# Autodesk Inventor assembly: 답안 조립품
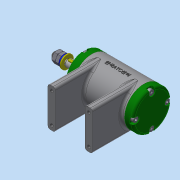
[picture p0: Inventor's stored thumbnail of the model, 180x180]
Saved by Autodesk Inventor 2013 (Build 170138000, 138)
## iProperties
Created: 2020-07
Part Number: 답안 조립품
Document SubType Name: Assembly
Designer: dgall
Author: dgall
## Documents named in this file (15)
- C:\Users\dgall\Desktop\700706V1017\답안 조립품.iam
- C:\Users\dgall\Desktop\700706V1017\본체.ipt
- C:\Users\dgall\Desktop\700706V1017\베어링 6002.ipt
- C:\Users\dgall\Desktop\700706V1017\뒤커버.ipt
- C:\Users\dgall\Desktop\700706V1017\앞커버.ipt
- C:\Users\dgall\Desktop\700706V1017\축.ipt
- C:\Users\dgall\Desktop\700706V1017\오일 실 15 25 7.ipt
- C:\Users\dgall\Desktop\700706V1017\키 3x3x12.ipt
- C:\Users\dgall\Desktop\700706V1017\V벨트풀리.ipt
- C:\Users\dgall\Desktop\700706V1017\와셔 8x17.ipt
- C:\Users\dgall\Desktop\700706V1017\스프링와셔 8.ipt
- C:\Users\dgall\Desktop\700706V1017\너트 M8.ipt
- C:\Users\dgall\Desktop\700706V1017\와셔 6x11.5.ipt
- C:\Users\dgall\Desktop\700706V1017\볼트 M6x8.ipt
- C:\Users\dgall\Desktop\700706V1017\볼트 M4x12.ipt
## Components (1 placed, 1 different names)
1. V벨트풀리:1
